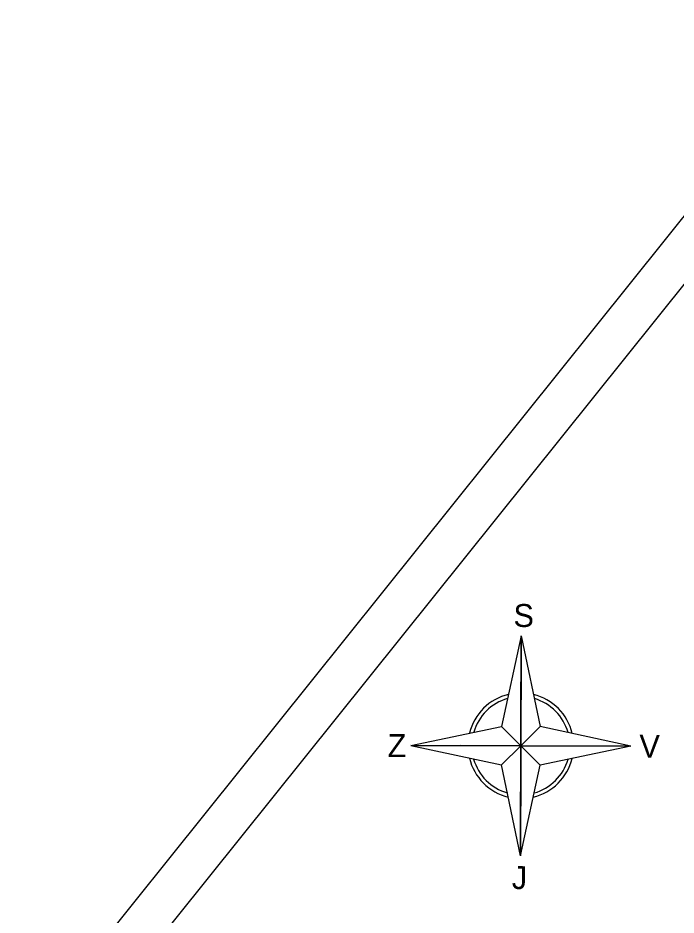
# Model space of a CAD drawing. Extents: x -541654 to -535721, y -1185255 to -1179094.
# Drawn here: x -539667 to -538738, y -1180360 to -1179094 of the extents above; entities that cross this region are included whole.
import ezdxf

# ---------------------------------------------------------------- set-up
doc = ezdxf.new("R2010")
doc.units = 0
doc.layers.add('Default', color=7, linetype='Continuous')

msp = doc.modelspace()

# ---------------------------------------------------------------- linework, layer by layer
at = {"layer": 'Default'}
for p, q in [((-538956.6, -1179965.9), (-538984.1, -1180093.9)), ((-538956.6, -1179965.9), (-538984.1, -1180093.9)), ((-538956.6, -1179965.9), (-538957.1, -1180147.4)), ((-538956.9, -1180095), (-538956.6, -1179965.9)), ((-538956.6, -1179965.9), (-538929.7, -1180094.1)), ((-539112.3, -1180120.8), (-538984.1, -1180093.9)), ((-538984.1, -1180093.9), (-538957, -1180121.2)), ((-538984.1, -1180093.9), (-538957, -1180121.2)), ((-538957.4, -1180276.5), (-538956.9, -1180095)), ((-538929.7, -1180094.1), (-538957, -1180121.2)), ((-538929.7, -1180094.1), (-538957, -1180121.2)), ((-538957, -1180121.2), (-538956.9, -1180095)), ((-538801.7, -1180121.6), (-538929.7, -1180094.1)), ((-538801.7, -1180121.6), (-538929.7, -1180094.1)), ((-539112.3, -1180120.8), (-538930.8, -1180121.3)), ((-539112.3, -1180120.8), (-538984.3, -1180148.3)), ((-539112.3, -1180120.8), (-538984.3, -1180148.3)), ((-538983.2, -1180121.1), (-539112.3, -1180120.8)), ((-539015.4, -1180121.1), (-539042.4, -1180121)), ((-538984.3, -1180148.3), (-538957, -1180121.2)), ((-538984.3, -1180148.3), (-538957, -1180121.2)), ((-538801.7, -1180121.6), (-538983.2, -1180121.1)), ((-538957, -1180121.2), (-538983.2, -1180121.1)), ((-538957, -1180121.2), (-538957.4, -1180276.5)), ((-538929.9, -1180148.5), (-538957, -1180121.2)), ((-538957, -1180121.2), (-538801.7, -1180121.6)), ((-538929.9, -1180148.5), (-538957, -1180121.2)), ((-538801.7, -1180121.6), (-538929.9, -1180148.5)), ((-538898.6, -1180121.4), (-538871.6, -1180121.4)), ((-538957.4, -1180276.5), (-538984.3, -1180148.3)), ((-538957.4, -1180276.5), (-538929.9, -1180148.5)), ((-538957.4, -1180276.5), (-538929.9, -1180148.5)), ((-538957.1, -1180179.6), (-538957.2, -1180206.6))]:
    msp.add_line(p, q, dxfattribs=at)
for points in [[(-535721.4, -1181322.7), (-538502.4, -1179093.8), (-541654.5, -1183026.4), (-538873.5, -1185255.4)], [(-535805.8, -1181332), (-538493.1, -1179178.1), (-541570.1, -1183017.1), (-538882.8, -1185171.1)]]:
    msp.add_lwpolyline(points, close=True, dxfattribs=at)
for radius, start, end in [(74.6, 103.4852, 166.2164), (74.6, 13.4852, 76.2164), (69.2, 105.6487, 164.0529), (69.2, 15.6487, 74.0529), (74.6, 193.4852, 256.2164), (69.2, 195.6487, 254.0529), (74.6, 283.4852, 346.2164), (69.2, 285.6487, 344.0529)]:
    msp.add_arc((-538957, -1180121.2), radius, start, end, dxfattribs=at)

# ---------------------------------------------------------------- texts
for s, p in [('S', (-538967.5, -1179953.5)), ('Z', (-539145.1, -1180137.1)), ('V', (-538789.7, -1180138.1)), ('J', (-538969.8, -1180323.5))]:
    msp.add_text(s, height=32.4, rotation=359.8508, dxfattribs=at).set_placement(p)

doc.saveas('drawing.dxf')
